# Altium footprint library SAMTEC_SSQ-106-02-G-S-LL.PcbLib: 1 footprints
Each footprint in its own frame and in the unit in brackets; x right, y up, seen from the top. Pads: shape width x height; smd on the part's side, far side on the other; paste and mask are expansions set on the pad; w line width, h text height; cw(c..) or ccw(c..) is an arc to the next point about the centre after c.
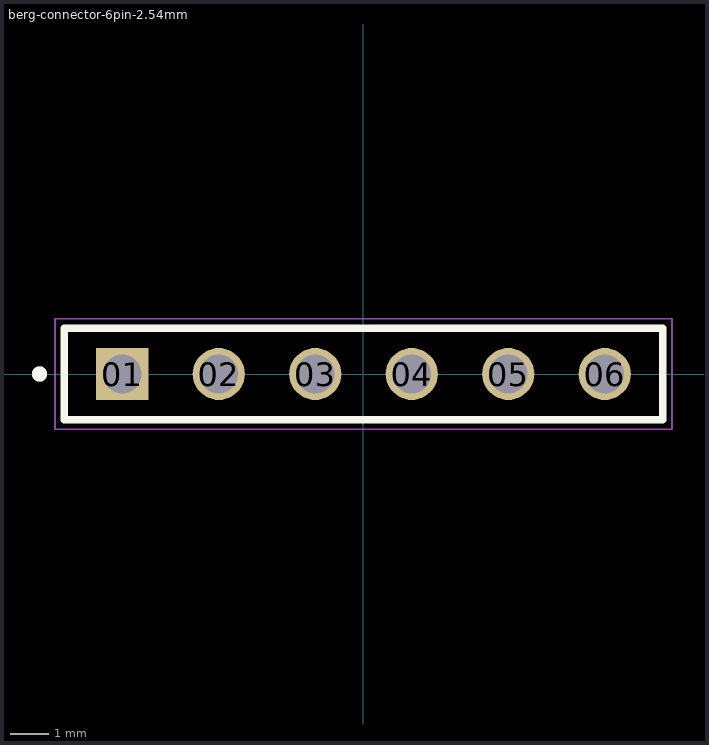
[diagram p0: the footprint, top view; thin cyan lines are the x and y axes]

## berg-connector-6pin-2.54mm [mm] "berg-connector-6pin-2.54mm"
pads (6):
  rect 1.37x1.37 / inner round 1.37 / far side rect 1.37x1.37 hole 1.02: 01(-6.35,0)
  round 1.37 hole 1.02: 02(-3.81,0) 03(-1.27,0) 04(1.27,0) 05(3.81,0) 06(6.35,0)
Top Overlay:
  circle w0.2: c-8.525,0 r0.1
  lines w0.2: -7.875,-1.205 -7.875,1.205 7.875,1.205 7.875,-1.205 -7.875,-1.205
Mechanical 13:
  circle w0.2: c-8.525,0 r0.1
  lines w0.1: -7.875,-1.205 -7.875,1.205 ; -7.875,-1.205 7.875,-1.205 ; -7.875,-1.205 -7.875,1.205 ; -7.875,1.205 7.875,1.205 ; -7.875,1.205 7.875,1.205 ; 7.875,-1.205 7.875,1.205 ; 7.875,-1.205 7.875,1.205
Mechanical 15:
  lines w0.05: -8.125,-1.455 -8.125,1.455 8.125,1.455 8.125,-1.455 -8.125,-1.455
